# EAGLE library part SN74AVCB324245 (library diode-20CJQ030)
Ti's SN74AVCB324245 32-BIT DUAL-SUPPLY BUS TRANSCEIVER WITH CONFIGURABLE VOLTAGE TRANSLATION AND 3-STATE OUTPUTS Description: This 32-bit noninverting bus transceiver uses two separate configurable power-supply rails. The A port is designed to track VCCA. VCCA accepts any supply voltage from 1.4 V to 3.6 V. The B port is designed to track VCCB. VCCB accepts any supply voltage from 1.4 V to 3.6 V. This allows for universal low-voltage bidirectional translation between any of the 1.5-V, 1.8-V, 2.5-V, and 3.3-V voltage nodes. The SN74AVCB324245 is designed for asynchronous communication between data buses. The device transmits data from the A bus to the B bus or from the B bus to the A bus, depending on the logic level at the direction-control (DIR) input. The output-enable (OE) input can be used to disable the outputs so the buses are effectively isolated. The SN74AVCB324245 is designed so that the control pins (1DIR, 2DIR, 1OE, and 2OE) are supplied by VCCB. To ensure the high-impedance state during power up or power down, OE shall be tied to VCCB through a pullup resistor; the minimum value of the resistor is determined by the current-sinking capability of the driver. This device is fully specified for partial-power-down applications using Ioff. The Ioff circuitry disables the outputs, preventing damaging current backflow through the device when it is powered down. If either VCC input is at GND, both ports are in the high-impedance state. Features: Member of the Texas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
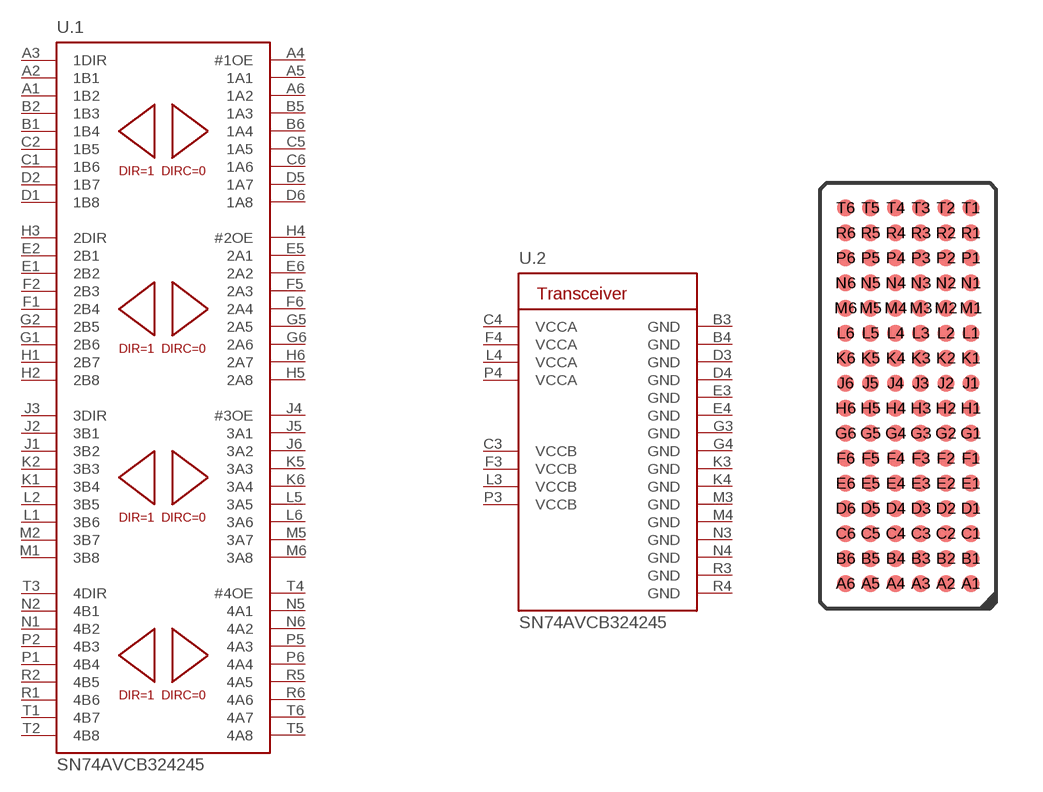
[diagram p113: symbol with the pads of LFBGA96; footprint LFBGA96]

Designator prefix U; gates .1=SN74AVCB324245 .2=SN74AVC324245_PWR

## SN74AVCB324245-GKE  [LFBGA96]
A1  .1:1B2
A2  .1:1B1
A3  .1:1DIR  in
A4  .1:#1OE  in
A5  .1:1A1
A6  .1:1A2
B1  .1:1B4
B2  .1:1B3
B3  .2:GND  pwr
B4  .2:GND  pwr
B5  .1:1A3
B6  .1:1A4
C1  .1:1B6
C2  .1:1B5
C3  .2:VCCB  pwr
C4  .2:VCCA  pwr
C5  .1:1A5
C6  .1:1A6
D1  .1:1B8
D2  .1:1B7
D3  .2:GND  pwr
D4  .2:GND  pwr
D5  .1:1A7
D6  .1:1A8
E1  .1:2B2
E2  .1:2B1
E3  .2:GND  pwr
E4  .2:GND  pwr
E5  .1:2A1
E6  .1:2A2
F1  .1:2B4
F2  .1:2B3
F3  .2:VCCB  pwr
F4  .2:VCCA  pwr
F5  .1:2A3
F6  .1:2A4
G1  .1:2B6
G2  .1:2B5
G3  .2:GND  pwr
G4  .2:GND  pwr
G5  .1:2A5
G6  .1:2A6
H1  .1:2B7
H2  .1:2B8
H3  .1:2DIR  in
H4  .1:#2OE  in
H5  .1:2A8
H6  .1:2A7
J1  .1:3B2
J2  .1:3B1
J3  .1:3DIR  in
J4  .1:#3OE  in
J5  .1:3A1
J6  .1:3A2
K1  .1:3B4
K2  .1:3B3
K3  .2:GND  pwr
K4  .2:GND  pwr
K5  .1:3A3
K6  .1:3A4
L1  .1:3B6
L2  .1:3B5
L3  .2:VCCB  pwr
L4  .2:VCCA  pwr
L5  .1:3A5
L6  .1:3A6
M1  .1:3B8
M2  .1:3B7
M3  .2:GND  pwr
M4  .2:GND  pwr
M5  .1:3A7
M6  .1:3A8
N1  .1:4B2  in
N2  .1:4B1  in
N3  .2:GND  pwr
N4  .2:GND  pwr
N5  .1:4A1  in
N6  .1:4A2  in
P1  .1:4B4  in
P2  .1:4B3  in
P3  .2:VCCB  pwr
P4  .2:VCCA  pwr
P5  .1:4A3  in
P6  .1:4A4  in
R1  .1:4B6  in
R2  .1:4B5  in
R3  .2:GND  pwr
R4  .2:GND  pwr
R5  .1:4A5  in
R6  .1:4A6  in
T1  .1:4B7  in
T2  .1:4B8  in
T3  .1:4DIR  in
T4  .1:#4OE  in
T5  .1:4A8  in
T6  .1:4A7  in

## Footprint LFBGA96 (pad centres in mm)
Ti's Package LFBGA-96
smd 0.55 x 0.55: A1 2,-6; A2 1.2,-6; A3 0.4,-6; A4 -0.4,-6; A5 -1.2,-6; A6 -2,-6; B1 2,-5.2; B2 1.2,-5.2; B3 0.4,-5.2; B4 -0.4,-5.2; B5 -1.2,-5.2; B6 -2,-5.2; C1 2,-4.4; C2 1.2,-4.4; C3 0.4,-4.4; C4 -0.4,-4.4; C5 -1.2,-4.4; C6 -2,-4.4; D1 2,-3.6; D2 1.2,-3.6; D3 0.4,-3.6; D4 -0.4,-3.6; D5 -1.2,-3.6; D6 -2,-3.6; E1 2,-2.8; E2 1.2,-2.8; E3 0.4,-2.8; E4 -0.4,-2.8; E5 -1.2,-2.8; E6 -2,-2.8; F1 2,-2; F2 1.2,-2; F3 0.4,-2; F4 -0.4,-2; F5 -1.2,-2; F6 -2,-2; G1 2,-1.2; G2 1.2,-1.2; G3 0.4,-1.2; G4 -0.4,-1.2; G5 -1.2,-1.2; G6 -2,-1.2; H1 2,-0.4; H2 1.2,-0.4; H3 0.4,-0.4; H4 -0.4,-0.4; H5 -1.2,-0.4; H6 -2,-0.4; J1 2,0.4; J2 1.2,0.4; J3 0.4,0.4; J4 -0.4,0.4; J5 -1.2,0.4; J6 -2,0.4; K1 2,1.2; K2 1.2,1.2; K3 0.4,1.2; K4 -0.4,1.2; K5 -1.2,1.2; K6 -2,1.2; L1 2,2; L2 1.2,2; L3 0.4,2; L4 -0.4,2; L5 -1.2,2; L6 -2,2; M1 2,2.8; M2 1.2,2.8; M3 0.4,2.8; M4 -0.4,2.8; M5 -1.2,2.8; M6 -2,2.8; N1 2,3.6; N2 1.2,3.6; N3 0.4,3.6; N4 -0.4,3.6; N5 -1.2,3.6; N6 -2,3.6; P1 2,4.4; P2 1.2,4.4; P3 0.4,4.4; P4 -0.4,4.4; P5 -1.2,4.4; P6 -2,4.4; R1 2,5.2; R2 1.2,5.2; R3 0.4,5.2; R4 -0.4,5.2; R5 -1.2,5.2; R6 -2,5.2; T1 2,6; T2 1.2,6; T3 0.4,6; T4 -0.4,6; T5 -1.2,6; T6 -2,6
